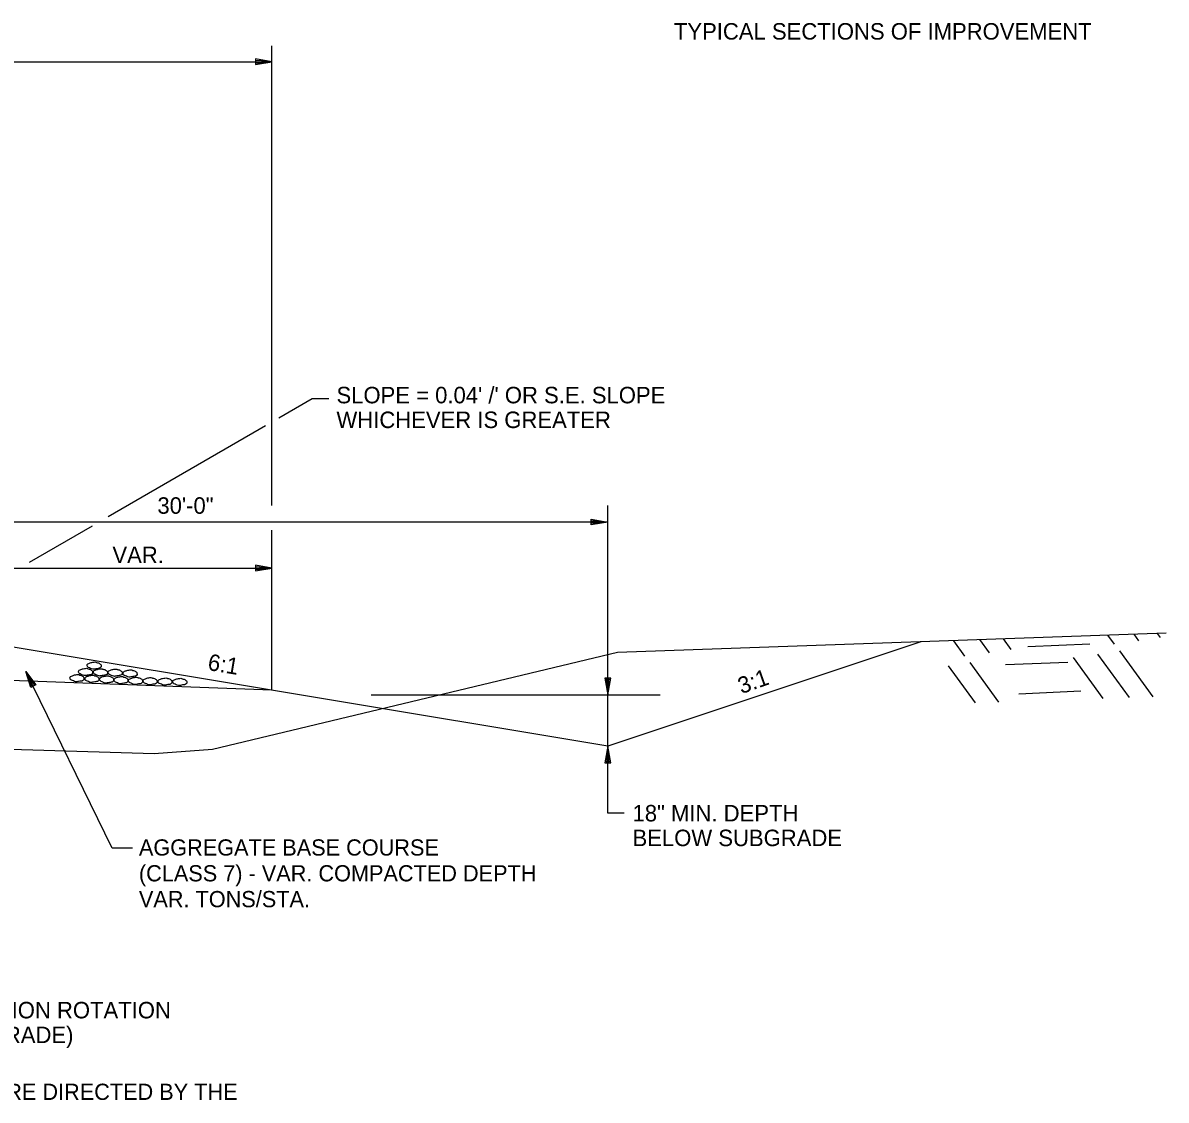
# Model space of a CAD drawing. Extents: x 1461846 to 1462006, y 1686171 to 1686805.
# Drawn here: x 1461963.23 to 1462004.83, y 1686495.17 to 1686534.38 of the extents above; entities that cross this region are included whole.
import ezdxf

# ---------------------------------------------------------------- set-up
doc = ezdxf.new("R2010")
doc.units = 0
for name, color, linetype in [('1', 7, 'Continuous'), ('10', 7, 'Continuous'), ('19', 7, 'Continuous'), ('20', 7, 'Continuous'), ('R_Draft', 7, 'Continuous')]:
    doc.layers.add(name, color=color, linetype=linetype)

# ---------------------------------------------------------------- blocks, each defined once
blk = doc.blocks.new('ROCKS')
at = {"layer": '1'}
blk.add_spline([(0.013, 0.06), (0.053, 0.053), (0.107, 0.033), (0.133, 0.013), (0.133, -0.007), (0.12, -0.033), (0.107, -0.04), (0.073, -0.053), (0.033, -0.067), (0.013, -0.067), (-0.02, -0.06), (-0.06, -0.053), (-0.087, -0.047), (-0.113, -0.02), (-0.113, -0.007), (-0.107, 0.02), (-0.087, 0.033), (-0.067, 0.047), (-0.033, 0.053), (-0.02, 0.06), (0.013, 0.06)], degree=3, dxfattribs=at)

msp = doc.modelspace()

# ---------------------------------------------------------------- linework, layer by layer
at = {"layer": '19'}
for p, q in [((1462002.948, 1686511.761), (1462002.711, 1686512.092)), ((1462003.84, 1686511.885), (1462003.666, 1686512.123)), ((1462004.631, 1686512.005), (1462004.52, 1686512.151)), ((1461997.506, 1686511.329), (1461997.105, 1686511.889)), ((1461998.398, 1686511.453), (1461998.049, 1686511.929)), ((1461999.189, 1686511.573), (1461998.913, 1686511.958)), ((1462002.06, 1686511.759), (1461999.801, 1686511.668)), ((1462002.546, 1686509.787), (1462001.46, 1686511.282)), ((1462003.501, 1686509.819), (1462002.352, 1686511.406)), ((1462004.355, 1686509.846), (1462003.143, 1686511.526)), ((1461997.894, 1686509.626), (1461996.909, 1686510.974)), ((1461998.748, 1686509.654), (1461997.7, 1686511.093)), ((1462001.253, 1686511.102), (1461998.984, 1686511.009)), ((1461966.474, 1686504.335), (1461963.34, 1686510.774)), ((1461963.517, 1686510.192), (1461963.34, 1686510.774)), ((1461963.34, 1686510.774), (1461963.704, 1686510.285)), ((1461963.561, 1686510.215), (1461963.397, 1686510.624)), ((1461963.422, 1686510.637), (1461963.655, 1686510.264)), ((1461963.704, 1686510.285), (1461963.517, 1686510.192)), ((1462001.732, 1686510.048), (1461999.475, 1686509.946)), ((1461967.211, 1686504.335), (1461966.474, 1686504.335))]:
    msp.add_line(p, q, dxfattribs=at)
at = {"layer": '20'}
for p, q in [((1461972.291, 1686521.977), (1461972.291, 1686533.547)), ((1461875.769, 1686532.965), (1461972.291, 1686532.965)), ((1461971.691, 1686533.07), (1461971.691, 1686532.86)), ((1461972.291, 1686532.965), (1461971.691, 1686533.07)), ((1461972.131, 1686532.98), (1461971.691, 1686533.015)), ((1461971.691, 1686532.86), (1461972.291, 1686532.965)), ((1461971.691, 1686532.91), (1461972.131, 1686532.95)), ((1461972.291, 1686516.811), (1461972.291, 1686521.977)), ((1461972.291, 1686510.087), (1461972.291, 1686515.911)), ((1461962.514, 1686514.532), (1461972.291, 1686514.532)), ((1461971.691, 1686514.638), (1461971.691, 1686514.428)), ((1461972.291, 1686514.532), (1461971.691, 1686514.638)), ((1461972.131, 1686514.547), (1461971.691, 1686514.583)), ((1461971.691, 1686514.428), (1461972.291, 1686514.532)), ((1461971.691, 1686514.478), (1461972.131, 1686514.517))]:
    msp.add_line(p, q, dxfattribs=at)
at = {"layer": 'R_Draft'}
for p, q in [((1461984.514, 1686509.883), (1461984.514, 1686516.811)), ((1461984.514, 1686516.211), (1461954.514, 1686516.211)), ((1461983.914, 1686516.106), (1461983.914, 1686516.316)), ((1461983.914, 1686516.316), (1461984.514, 1686516.211)), ((1461983.914, 1686516.261), (1461984.354, 1686516.226)), ((1461984.514, 1686516.211), (1461983.914, 1686516.106)), ((1461984.354, 1686516.196), (1461983.914, 1686516.156)), ((1461984.514, 1686508.05), (1461962.514, 1686511.716)), ((1461995.906, 1686511.847), (1461984.514, 1686508.05)), ((1461984.619, 1686510.526), (1461984.409, 1686510.526)), ((1461984.409, 1686510.526), (1461984.514, 1686509.926)), ((1461984.459, 1686510.526), (1461984.499, 1686510.086)), ((1461984.514, 1686509.926), (1461984.619, 1686510.526)), ((1461984.529, 1686510.086), (1461984.564, 1686510.526)), ((1461975.908, 1686509.926), (1461986.423, 1686509.926)), ((1461984.514, 1686505.613), (1461984.514, 1686509.883)), ((1461984.514, 1686508.05), (1461984.409, 1686507.45)), ((1461984.499, 1686507.89), (1461984.464, 1686507.45)), ((1461984.619, 1686507.45), (1461984.514, 1686508.05)), ((1461984.569, 1686507.45), (1461984.529, 1686507.89)), ((1461984.409, 1686507.45), (1461984.619, 1686507.45)), ((1461985.114, 1686505.613), (1461984.514, 1686505.613))]:
    msp.add_line(p, q, dxfattribs=at)
for points in [[(1461974.361, 1686520.699), (1461973.761, 1686520.699), (1461972.547, 1686519.996)], [(1461972.06, 1686519.715), (1461966.328, 1686516.398)], [(1461965.744, 1686516.06), (1461963.462, 1686514.739)], [(1462004.832, 1686512.162), (1461984.872, 1686511.458), (1461970.134, 1686507.926), (1461968, 1686507.772), (1461963.59, 1686507.904), (1461955.708, 1686508.135), (1461934.695, 1686508.743), (1461919.514, 1686513.165), (1461918.223, 1686513.06), (1461917.452, 1686512.972), (1461899.751, 1686513.614), (1461895.514, 1686514.053), (1461888.778, 1686512.7), (1461874.437, 1686508.371)], [(1461972.291, 1686510.087), (1461919.514, 1686512.04)]]:
    msp.add_lwpolyline(points, dxfattribs=at)

# ---------------------------------------------------------------- block references
at = {"layer": '19', "xscale": 2.061136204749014, "yscale": -2.061136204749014, "rotation": 178.63717054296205}
for p in [(1461965.532, 1686510.757), (1461965.842, 1686510.989), (1461966.073, 1686510.744), (1461966.607, 1686510.732), (1461967.149, 1686510.703), (1461965.218, 1686510.532), (1461965.763, 1686510.51), (1461966.296, 1686510.487), (1461966.819, 1686510.462), (1461967.35, 1686510.434), (1461967.877, 1686510.422), (1461968.421, 1686510.409), (1461968.959, 1686510.396)]:
    msp.add_blockref('ROCKS', p, dxfattribs=at)

# ---------------------------------------------------------------- texts
at = {"layer": '1'}
msp.add_text('TYPICAL SECTIONS OF IMPROVEMENT', height=0.6, dxfattribs=at).set_placement((1461986.919, 1686533.771))
at = {"layer": '10'}
msp.add_text('TO BE USED IF AND WHERE DIRECTED BY THE ', height=0.59001, rotation=360, dxfattribs=at).set_placement((1461952.979, 1686495.176))
at = {"layer": '19'}
for s, p in [('AGGREGATE BASE COURSE', (1461967.45, 1686504.07)), ('(CLASS 7) - VAR. COMPACTED DEPTH', (1461967.45, 1686503.13)), ('VAR. TONS/STA.', (1461967.45, 1686502.19))]:
    msp.add_text(s, height=0.59001, rotation=360, dxfattribs=at).set_placement(p)
at = {"layer": 'R_Draft'}
for s, p in [("SLOPE = 0.04' /' OR S.E. SLOPE", (1461974.64, 1686520.531)), ('WHICHEVER IS GREATER', (1461974.64, 1686519.631)), ('30\'-0"', (1461968.123, 1686516.511)), ('18" MIN. DEPTH', (1461985.414, 1686505.313)), ('BELOW SUBGRADE', (1461985.414, 1686504.413))]:
    msp.add_text(s, height=0.6, dxfattribs=at).set_placement(p)
for s, rotation, p in [('VAR.', 360, (1461966.486, 1686514.715)), ('6:1', 350.5175, (1461969.927, 1686510.829)), ('3:1', 19.5057, (1461989.376, 1686509.943)), ('POINT OF SUPERELEVATION ROTATION', 359.9954, (1461952.966, 1686498.145)), ("(0.59' BELOW PROFILE GRADE)", 359.9954, (1461952.966, 1686497.245))]:
    msp.add_text(s, height=0.6, rotation=rotation, dxfattribs=at).set_placement(p)

doc.saveas('drawing.dxf')
